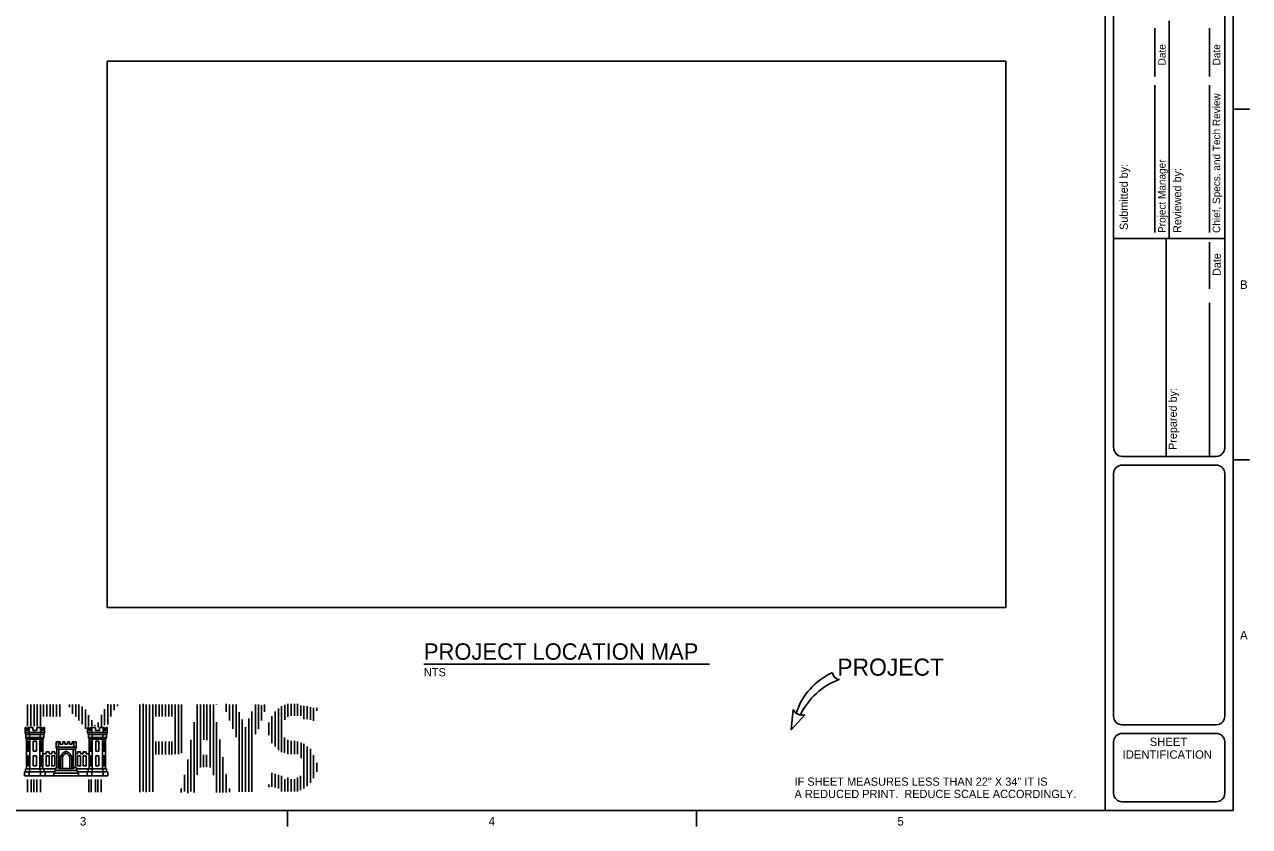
# Model space of a CAD drawing. Extents: x -1.36 to 2.79, y 0.03 to 1.79.
# Drawn here: x 1.298 to 2.791, y 0.043 to 1.02 of the extents above; entities that cross this region are included whole.
import ezdxf

# ---------------------------------------------------------------- set-up
doc = ezdxf.new("R2010")
doc.units = 0
for name, color, linetype in [('FL9BG-BS0001 - G-ANNO-TEXT', 7, 'Continuous'), ('G-ANNO-SYMB', 7, 'Continuous'), ('G-ANNO-TEXT', 7, 'Continuous'), ('G-ANNO-TTLB', 7, 'Continuous')]:
    doc.layers.add(name, color=color, linetype=linetype)

msp = doc.modelspace()

# ---------------------------------------------------------------- linework, layer by layer
at = {"layer": 'G-ANNO-SYMB'}
msp.add_line((2.1329, 0.2408), (1.7848, 0.2408), dxfattribs=at)
msp.add_lwpolyline([(1.399, 0.9753), (2.4939, 0.9753), (2.4939, 0.3098), (1.399, 0.3098)], close=True, dxfattribs=at)
for points in [[(2.249, 0.1789), (2.2323, 0.1608), (2.2348, 0.1854)], [(2.249, 0.1789), (2.2323, 0.1608), (2.2348, 0.1853)], [(2.2434, 0.1787), (2.2434, 0.1787)], [(2.2434, 0.1787), (2.2434, 0.1787)]]:
    msp.add_lwpolyline(points, dxfattribs=at)
for centre, radius, start, end in [((2.3157, 0.1561), 0.0813, 114.1414, 162.1394), ((2.3157, 0.1561), 0.0813, 114.1414, 162.1394), ((2.2914, 0.231), 0.00894, 184.9032, 266.6327), ((2.2914, 0.231), 0.00894, 184.9032, 266.6327), ((2.3203, 0.1422), 0.0851, 110.2554, 154.6222), ((2.3203, 0.1422), 0.0851, 110.2554, 154.6168), ((2.2457, 0.1907), 0.0122, 205.9222, 285.6211), ((2.2457, 0.1907), 0.0122, 205.9222, 258.8897), ((2.2457, 0.1907), 0.0122, 232.4837, 258.8897), ((2.2457, 0.1907), 0.0122, 258.8991, 285.6211), ((2.3203, 0.1422), 0.0851, 154.6168, 154.6222)]:
    msp.add_arc(centre, radius, start, end, dxfattribs=at)
at = {"layer": 'G-ANNO-TEXT'}
for p, q in [((1.3021, 0.1652), (1.3021, 0.1916)), ((1.306, 0.1652), (1.306, 0.1916)), ((1.3099, 0.1652), (1.3099, 0.1916)), ((1.3138, 0.1649), (1.3138, 0.1916)), ((1.3177, 0.1652), (1.3177, 0.1916)), ((1.3216, 0.1769), (1.3216, 0.1916)), ((1.3255, 0.1769), (1.3255, 0.1916)), ((1.3294, 0.1769), (1.3294, 0.1916)), ((1.3333, 0.1769), (1.3333, 0.1916)), ((1.3372, 0.1769), (1.3372, 0.1916)), ((1.3412, 0.1769), (1.3412, 0.1916)), ((1.3529, 0.1883), (1.3529, 0.1916)), ((1.3568, 0.1803), (1.3568, 0.1916)), ((1.3607, 0.1769), (1.3607, 0.1916)), ((1.3646, 0.172), (1.3646, 0.1916)), ((1.3685, 0.1674), (1.3685, 0.1889)), ((1.3724, 0.1852), (1.3724, 0.1618)), ((1.3958, 0.1664), (1.3958, 0.1858)), ((1.3997, 0.167), (1.3997, 0.1919)), ((1.4036, 0.1769), (1.4036, 0.1916)), ((1.4076, 0.1846), (1.4076, 0.1919)), ((1.4115, 0.1895), (1.4115, 0.1916)), ((1.4388, 0.0847), (1.4388, 0.1916)), ((1.4427, 0.0853), (1.4427, 0.1922)), ((1.4466, 0.0847), (1.4466, 0.1916)), ((1.4505, 0.085), (1.4505, 0.1916)), ((1.4544, 0.085), (1.4544, 0.1916)), ((1.4583, 0.1769), (1.4583, 0.1916)), ((1.4622, 0.1769), (1.4622, 0.1916)), ((1.4661, 0.1769), (1.4661, 0.1916)), ((1.47, 0.1769), (1.47, 0.1916)), ((1.4739, 0.1769), (1.4739, 0.1916)), ((1.4779, 0.1769), (1.4779, 0.1916)), ((1.4818, 0.1311), (1.4818, 0.1916)), ((1.4857, 0.1311), (1.4857, 0.1916)), ((1.4896, 0.1323), (1.4896, 0.1916)), ((1.5088, 0.1057), (1.5088, 0.1913)), ((1.5127, 0.1148), (1.5127, 0.1913)), ((1.5166, 0.1484), (1.5166, 0.1913)), ((1.5205, 0.1481), (1.5205, 0.1913)), ((1.5244, 0.1148), (1.5244, 0.1913)), ((1.5283, 0.1055), (1.5283, 0.1913)), ((1.5322, 0.191), (1.5322, 0.1913)), ((1.5439, 0.1824), (1.5439, 0.1922)), ((1.548, 0.1721), (1.548, 0.1916)), ((1.5521, 0.1618), (1.5521, 0.1916)), ((1.5561, 0.1515), (1.5561, 0.1916)), ((1.5599, 0.085), (1.5599, 0.1821)), ((1.5752, 0.1913), (1.5752, 0.1916)), ((1.5752, 0.085), (1.5752, 0.183)), ((1.5796, 0.1553), (1.5796, 0.1916)), ((1.5833, 0.1615), (1.5833, 0.1913)), ((1.5871, 0.172), (1.5871, 0.1907)), ((1.5908, 0.1827), (1.5908, 0.1913)), ((1.6036, 0.1403), (1.6036, 0.183)), ((1.6075, 0.136), (1.6075, 0.1867)), ((1.6114, 0.1335), (1.6114, 0.1895)), ((1.6153, 0.1729), (1.6153, 0.191)), ((1.6192, 0.1763), (1.6192, 0.1922)), ((1.6231, 0.1775), (1.6231, 0.1922)), ((1.627, 0.1775), (1.627, 0.1922)), ((1.6309, 0.1775), (1.6309, 0.1922)), ((1.6348, 0.1775), (1.6348, 0.1901)), ((1.6387, 0.1738), (1.6387, 0.1898)), ((1.6426, 0.1895), (1.6426, 0.1738)), ((1.6466, 0.1883), (1.6466, 0.1726)), ((1.6505, 0.1726), (1.6505, 0.1876)), ((1.6544, 0.1836), (1.6544, 0.1876)), ((1.3763, 0.1652), (1.3763, 0.1784)), ((1.3802, 0.1652), (1.3802, 0.1723)), ((1.3841, 0.1655), (1.3841, 0.1664)), ((1.388, 0.164), (1.388, 0.1695)), ((1.3919, 0.1646), (1.3919, 0.179)), ((1.5049, 0.0844), (1.5049, 0.1699)), ((1.5322, 0.0841), (1.5322, 0.17)), ((1.5636, 0.085), (1.5636, 0.1732)), ((1.5717, 0.085), (1.5717, 0.1744)), ((1.5958, 0.1541), (1.5958, 0.1695)), ((1.5997, 0.1443), (1.5997, 0.1772)), ((1.6505, 0.1717), (1.6505, 0.1726)), ((1.299, 0.1634), (1.3005, 0.1634)), ((1.299, 0.1572), (1.299, 0.1634)), ((1.299, 0.1572), (1.3108, 0.1572)), ((1.299, 0.1572), (1.2999, 0.1551)), ((1.2999, 0.1551), (1.3108, 0.1551)), ((1.2999, 0.1551), (1.2999, 0.1514)), ((1.2999, 0.1514), (1.3108, 0.1514)), ((1.3008, 0.1492), (1.2999, 0.1514)), ((1.3005, 0.1634), (1.3005, 0.1597)), ((1.3005, 0.1597), (1.3024, 0.1597)), ((1.3005, 0.1572), (1.3015, 0.1572)), ((1.3024, 0.1634), (1.3083, 0.1634)), ((1.3024, 0.1634), (1.3024, 0.1597)), ((1.304, 0.1572), (1.304, 0.1634)), ((1.3043, 0.1551), (1.304, 0.1572)), ((1.3043, 0.1551), (1.3043, 0.1514)), ((1.3043, 0.1514), (1.3046, 0.1492)), ((1.3083, 0.1597), (1.3083, 0.1634)), ((1.3083, 0.1597), (1.3108, 0.1597)), ((1.3133, 0.1597), (1.3108, 0.1597)), ((1.3227, 0.1572), (1.3108, 0.1572)), ((1.3218, 0.1551), (1.3108, 0.1551)), ((1.3218, 0.1514), (1.3108, 0.1514)), ((1.3133, 0.1597), (1.3133, 0.1634)), ((1.3193, 0.1634), (1.3133, 0.1634)), ((1.3174, 0.1514), (1.3171, 0.1492)), ((1.3174, 0.1551), (1.3177, 0.1572)), ((1.3174, 0.1551), (1.3174, 0.1514)), ((1.3177, 0.1572), (1.3177, 0.1634)), ((1.3193, 0.1634), (1.3193, 0.1597)), ((1.3212, 0.1597), (1.3193, 0.1597)), ((1.3212, 0.1572), (1.3202, 0.1572)), ((1.3208, 0.1492), (1.3218, 0.1514)), ((1.3227, 0.1634), (1.3212, 0.1634)), ((1.3212, 0.1634), (1.3212, 0.1597)), ((1.3227, 0.1572), (1.3218, 0.1551)), ((1.3218, 0.1551), (1.3218, 0.1514)), ((1.3227, 0.1572), (1.3227, 0.1634)), ((1.3752, 0.1634), (1.3768, 0.1634)), ((1.3752, 0.1572), (1.3752, 0.1634)), ((1.3752, 0.1572), (1.3871, 0.1572)), ((1.3752, 0.1572), (1.3761, 0.1551)), ((1.3761, 0.1551), (1.3871, 0.1551)), ((1.3761, 0.1551), (1.3761, 0.1514)), ((1.3761, 0.1514), (1.3871, 0.1514)), ((1.3771, 0.1492), (1.3761, 0.1514)), ((1.3768, 0.1634), (1.3768, 0.1597)), ((1.3768, 0.1597), (1.3786, 0.1597)), ((1.3768, 0.1572), (1.3777, 0.1572)), ((1.3786, 0.1634), (1.3846, 0.1634)), ((1.3786, 0.1634), (1.3786, 0.1597)), ((1.3802, 0.1572), (1.3802, 0.1634)), ((1.3805, 0.1551), (1.3802, 0.1572)), ((1.3805, 0.1551), (1.3805, 0.1514)), ((1.3805, 0.1514), (1.3808, 0.1492)), ((1.3846, 0.1597), (1.3846, 0.1634)), ((1.3846, 0.1597), (1.3871, 0.1597)), ((1.3896, 0.1597), (1.3871, 0.1597)), ((1.399, 0.1572), (1.3871, 0.1572)), ((1.398, 0.1551), (1.3871, 0.1551)), ((1.398, 0.1514), (1.3871, 0.1514)), ((1.3896, 0.1597), (1.3896, 0.1634)), ((1.3955, 0.1634), (1.3896, 0.1634)), ((1.3936, 0.1514), (1.3933, 0.1492)), ((1.3936, 0.1551), (1.394, 0.1572)), ((1.3936, 0.1551), (1.3936, 0.1514)), ((1.394, 0.1572), (1.394, 0.1634)), ((1.3955, 0.1634), (1.3955, 0.1597)), ((1.3974, 0.1597), (1.3955, 0.1597)), ((1.3974, 0.1572), (1.3965, 0.1572)), ((1.3971, 0.1492), (1.398, 0.1514)), ((1.399, 0.1634), (1.3974, 0.1634)), ((1.3974, 0.1634), (1.3974, 0.1597)), ((1.399, 0.1572), (1.398, 0.1551)), ((1.398, 0.1551), (1.398, 0.1514)), ((1.399, 0.1572), (1.399, 0.1634)), ((1.5674, 0.085), (1.5674, 0.1637)), ((1.6151, 0.1326), (1.6151, 0.1511)), ((1.3008, 0.1492), (1.3108, 0.1492)), ((1.3008, 0.1492), (1.3008, 0.113)), ((1.3021, 0.1345), (1.3021, 0.1468)), ((1.3021, 0.1468), (1.3033, 0.1468)), ((1.3033, 0.1345), (1.3021, 0.1345)), ((1.3033, 0.1345), (1.3033, 0.1468)), ((1.3046, 0.1492), (1.3046, 0.113)), ((1.309, 0.1468), (1.309, 0.1345)), ((1.309, 0.1468), (1.3108, 0.1468)), ((1.309, 0.1345), (1.3108, 0.1345)), ((1.3208, 0.1492), (1.3108, 0.1492)), ((1.3127, 0.1468), (1.3108, 0.1468)), ((1.3127, 0.1345), (1.3108, 0.1345)), ((1.3127, 0.1468), (1.3127, 0.1345)), ((1.3171, 0.1492), (1.3171, 0.113)), ((1.3183, 0.1345), (1.3183, 0.1468)), ((1.3196, 0.1468), (1.3183, 0.1468)), ((1.3183, 0.1345), (1.3196, 0.1345)), ((1.3196, 0.1345), (1.3196, 0.1468)), ((1.3208, 0.1492), (1.3208, 0.113)), ((1.3368, 0.1461), (1.3368, 0.1394)), ((1.3368, 0.1461), (1.3418, 0.1461)), ((1.3368, 0.1394), (1.349, 0.1394)), ((1.3377, 0.1372), (1.3368, 0.1394)), ((1.3374, 0.1372), (1.349, 0.1372)), ((1.3377, 0.1375), (1.3377, 0.1148)), ((1.3396, 0.1461), (1.3396, 0.1394)), ((1.3402, 0.1136), (1.3402, 0.1372)), ((1.3418, 0.1461), (1.3418, 0.1431)), ((1.3418, 0.1431), (1.3449, 0.1431)), ((1.3449, 0.1461), (1.3449, 0.1431)), ((1.3449, 0.1461), (1.3474, 0.1461)), ((1.3474, 0.1431), (1.3474, 0.1461)), ((1.3474, 0.1431), (1.3505, 0.1431)), ((1.3611, 0.1394), (1.349, 0.1394)), ((1.3605, 0.1372), (1.349, 0.1372)), ((1.3505, 0.1431), (1.3505, 0.1461)), ((1.353, 0.1461), (1.3505, 0.1461)), ((1.353, 0.1461), (1.353, 0.1431)), ((1.3562, 0.1431), (1.353, 0.1431)), ((1.3562, 0.1461), (1.3562, 0.1431)), ((1.3611, 0.1461), (1.3562, 0.1461)), ((1.3577, 0.1136), (1.3577, 0.1372)), ((1.3583, 0.1461), (1.3583, 0.1394)), ((1.3602, 0.1372), (1.3611, 0.1394)), ((1.3602, 0.1375), (1.3602, 0.1148)), ((1.3611, 0.1461), (1.3611, 0.1394)), ((1.3771, 0.1492), (1.3871, 0.1492)), ((1.3771, 0.1492), (1.3771, 0.113)), ((1.3783, 0.1345), (1.3783, 0.1468)), ((1.3783, 0.1468), (1.3796, 0.1468)), ((1.3796, 0.1345), (1.3783, 0.1345)), ((1.3796, 0.1345), (1.3796, 0.1468)), ((1.3808, 0.1492), (1.3808, 0.113)), ((1.3852, 0.1468), (1.3852, 0.1345)), ((1.3852, 0.1468), (1.3871, 0.1468)), ((1.3852, 0.1345), (1.3871, 0.1345)), ((1.3971, 0.1492), (1.3871, 0.1492)), ((1.389, 0.1468), (1.3871, 0.1468)), ((1.389, 0.1345), (1.3871, 0.1345)), ((1.389, 0.1468), (1.389, 0.1345)), ((1.3933, 0.1492), (1.3933, 0.113)), ((1.3946, 0.1345), (1.3946, 0.1468)), ((1.3958, 0.1468), (1.3946, 0.1468)), ((1.3946, 0.1345), (1.3958, 0.1345)), ((1.3958, 0.1345), (1.3958, 0.1468)), ((1.3971, 0.1492), (1.3971, 0.113)), ((1.4583, 0.1305), (1.4583, 0.1465)), ((1.4621, 0.1305), (1.4621, 0.1465)), ((1.4661, 0.1305), (1.4661, 0.1465)), ((1.4699, 0.1305), (1.4699, 0.1465)), ((1.4743, 0.1305), (1.4743, 0.1465)), ((1.4777, 0.1305), (1.4777, 0.1465)), ((1.501, 0.1485), (1.501, 0.0853)), ((1.5361, 0.0844), (1.5361, 0.1487)), ((1.6192, 0.1311), (1.6192, 0.1486)), ((1.623, 0.1311), (1.623, 0.1471)), ((1.627, 0.1311), (1.627, 0.1471)), ((1.6308, 0.1311), (1.6308, 0.1465)), ((1.6351, 0.1262), (1.6351, 0.1449)), ((1.6387, 0.089), (1.6387, 0.1434)), ((1.6426, 0.1403), (1.6426, 0.0921)), ((1.6466, 0.1375), (1.6466, 0.1369)), ((1.6466, 0.1366), (1.6466, 0.0961)), ((1.3021, 0.1166), (1.3021, 0.1289)), ((1.3033, 0.1289), (1.3021, 0.1289)), ((1.3033, 0.1166), (1.3033, 0.1289)), ((1.309, 0.1289), (1.309, 0.1166)), ((1.309, 0.1289), (1.3108, 0.1289)), ((1.3127, 0.1289), (1.3108, 0.1289)), ((1.3127, 0.1289), (1.3127, 0.1166)), ((1.3183, 0.1166), (1.3183, 0.1289)), ((1.3183, 0.1289), (1.3196, 0.1289)), ((1.3196, 0.1166), (1.3196, 0.1289)), ((1.3208, 0.1314), (1.3246, 0.1314)), ((1.3246, 0.1339), (1.3283, 0.1339)), ((1.3246, 0.1339), (1.3246, 0.1314)), ((1.3246, 0.1289), (1.3283, 0.1289)), ((1.3246, 0.1289), (1.3246, 0.1166)), ((1.3283, 0.1339), (1.3283, 0.1314)), ((1.3283, 0.1314), (1.3315, 0.1314)), ((1.3283, 0.1289), (1.3283, 0.1166)), ((1.3315, 0.1339), (1.3352, 0.1339)), ((1.3315, 0.1339), (1.3315, 0.1314)), ((1.3315, 0.1289), (1.3352, 0.1289)), ((1.3315, 0.1289), (1.3315, 0.1166)), ((1.3352, 0.1339), (1.3352, 0.1314)), ((1.3352, 0.1314), (1.3377, 0.1314)), ((1.3352, 0.1289), (1.3352, 0.1166)), ((1.3377, 0.1314), (1.3377, 0.1148)), ((1.3421, 0.1136), (1.3421, 0.1277)), ((1.3446, 0.1136), (1.3446, 0.1277)), ((1.3533, 0.1136), (1.3533, 0.1277)), ((1.3558, 0.1136), (1.3558, 0.1277)), ((1.3627, 0.1314), (1.3602, 0.1314)), ((1.3602, 0.1314), (1.3602, 0.1148)), ((1.3665, 0.1339), (1.3627, 0.1339)), ((1.3627, 0.1339), (1.3627, 0.1314)), ((1.3665, 0.1289), (1.3627, 0.1289)), ((1.3627, 0.1289), (1.3627, 0.1166)), ((1.3665, 0.1339), (1.3665, 0.1314)), ((1.3696, 0.1314), (1.3665, 0.1314)), ((1.3665, 0.1289), (1.3665, 0.1166)), ((1.3733, 0.1339), (1.3696, 0.1339)), ((1.3696, 0.1339), (1.3696, 0.1314)), ((1.3733, 0.1289), (1.3696, 0.1289)), ((1.3696, 0.1289), (1.3696, 0.1166)), ((1.3733, 0.1339), (1.3733, 0.1314)), ((1.3771, 0.1314), (1.3733, 0.1314)), ((1.3733, 0.1289), (1.3733, 0.1166)), ((1.3783, 0.1166), (1.3783, 0.1289)), ((1.3796, 0.1289), (1.3783, 0.1289)), ((1.3796, 0.1166), (1.3796, 0.1289)), ((1.3852, 0.1289), (1.3852, 0.1166)), ((1.3852, 0.1289), (1.3871, 0.1289)), ((1.389, 0.1289), (1.3871, 0.1289)), ((1.389, 0.1289), (1.389, 0.1166)), ((1.3946, 0.1166), (1.3946, 0.1289)), ((1.3946, 0.1289), (1.3958, 0.1289)), ((1.3958, 0.1166), (1.3958, 0.1289)), ((1.4971, 0.1243), (1.4971, 0.0835)), ((1.5163, 0.1151), (1.5163, 0.1302)), ((1.52, 0.1151), (1.52, 0.1302)), ((1.54, 0.0844), (1.54, 0.1273)), ((1.6505, 0.1019), (1.6505, 0.1299)), ((1.6544, 0.1093), (1.6544, 0.1203)), ((1.2983, 0.1093), (1.3108, 0.1093)), ((1.2983, 0.1044), (1.2983, 0.1093)), ((1.2996, 0.113), (1.3108, 0.113)), ((1.2996, 0.1093), (1.2996, 0.113)), ((1.3021, 0.1166), (1.3033, 0.1166)), ((1.304, 0.1044), (1.304, 0.1093)), ((1.3043, 0.1093), (1.3043, 0.113)), ((1.309, 0.1166), (1.3108, 0.1166)), ((1.3127, 0.1166), (1.3108, 0.1166)), ((1.3365, 0.113), (1.3108, 0.113)), ((1.3352, 0.1093), (1.3108, 0.1093)), ((1.3174, 0.1093), (1.3174, 0.113)), ((1.3177, 0.1044), (1.3177, 0.1093)), ((1.3196, 0.1166), (1.3183, 0.1166)), ((1.3221, 0.1093), (1.3221, 0.113)), ((1.3233, 0.1044), (1.3233, 0.1093)), ((1.3246, 0.1166), (1.3283, 0.1166)), ((1.3315, 0.1166), (1.3352, 0.1166)), ((1.3315, 0.1163), (1.3315, 0.116)), ((1.334, 0.108), (1.334, 0.1044)), ((1.334, 0.108), (1.349, 0.108)), ((1.3352, 0.1111), (1.349, 0.1111)), ((1.3352, 0.1111), (1.3352, 0.108)), ((1.3365, 0.1148), (1.3396, 0.1148)), ((1.3365, 0.1111), (1.3365, 0.1148)), ((1.3396, 0.1136), (1.3396, 0.1148)), ((1.3396, 0.1136), (1.349, 0.1136)), ((1.3583, 0.1136), (1.349, 0.1136)), ((1.3627, 0.1111), (1.349, 0.1111)), ((1.364, 0.108), (1.349, 0.108)), ((1.3583, 0.1136), (1.3583, 0.1148)), ((1.3615, 0.1148), (1.3583, 0.1148)), ((1.3615, 0.1111), (1.3615, 0.1148)), ((1.3615, 0.113), (1.3871, 0.113)), ((1.3665, 0.1166), (1.3627, 0.1166)), ((1.3627, 0.1111), (1.3627, 0.108)), ((1.3627, 0.1093), (1.3871, 0.1093)), ((1.364, 0.108), (1.364, 0.1044)), ((1.3665, 0.1163), (1.3665, 0.116)), ((1.3733, 0.1166), (1.3696, 0.1166)), ((1.3746, 0.1044), (1.3746, 0.1093)), ((1.3758, 0.1093), (1.3758, 0.113)), ((1.3783, 0.1166), (1.3796, 0.1166)), ((1.3802, 0.1044), (1.3802, 0.1093)), ((1.3805, 0.1093), (1.3805, 0.113)), ((1.3852, 0.1166), (1.3871, 0.1166)), ((1.389, 0.1166), (1.3871, 0.1166)), ((1.3983, 0.113), (1.3871, 0.113)), ((1.3996, 0.1093), (1.3871, 0.1093)), ((1.3936, 0.1093), (1.3936, 0.113)), ((1.394, 0.1044), (1.394, 0.1093)), ((1.3958, 0.1166), (1.3946, 0.1166)), ((1.3983, 0.1093), (1.3983, 0.113)), ((1.3996, 0.1044), (1.3996, 0.1093)), ((1.4932, 0.1058), (1.4932, 0.0856)), ((1.5439, 0.106), (1.5439, 0.1068)), ((1.5439, 0.0844), (1.5439, 0.1053)), ((1.5997, 0.0911), (1.5997, 0.1084)), ((1.6036, 0.0905), (1.6036, 0.1068)), ((1.6075, 0.0893), (1.6075, 0.1059)), ((1.6114, 0.0878), (1.6114, 0.1047)), ((1.6345, 0.0871), (1.6345, 0.1047)), ((1.2983, 0.1044), (1.3996, 0.1044)), ((1.3021, 0.0847), (1.3021, 0.1001)), ((1.3062, 0.0847), (1.3062, 0.1001)), ((1.3096, 0.0847), (1.3096, 0.1001)), ((1.3133, 0.0847), (1.3133, 0.1001)), ((1.3177, 0.0847), (1.3177, 0.1001)), ((1.334, 0.1044), (1.349, 0.1044)), ((1.364, 0.1044), (1.349, 0.1044)), ((1.3765, 0.0847), (1.3765, 0.1001)), ((1.3796, 0.0847), (1.3796, 0.1001)), ((1.3846, 0.0847), (1.3846, 0.1001)), ((1.3877, 0.0847), (1.3877, 0.1001)), ((1.3918, 0.0847), (1.3918, 0.1001)), ((1.5958, 0.0908), (1.5958, 0.0939)), ((1.6114, 0.0853), (1.6114, 0.1007)), ((1.6155, 0.0853), (1.6155, 0.1007)), ((1.6192, 0.0853), (1.6192, 0.1025)), ((1.623, 0.0853), (1.623, 0.1007)), ((1.627, 0.0853), (1.627, 0.1007)), ((1.6308, 0.0853), (1.6308, 0.1025)), ((1.4893, 0.0844), (1.4893, 0.089)), ((1.5478, 0.0847), (1.5478, 0.089)), ((2.75, 0.0625), (2.75, 0.0625)), ((2.7708, 0.0625), (2.7708, 0.0625)), ((2.7708, 0.0625), (2.7708, 0.0625)), ((2.7708, 0.0625), (2.7708, 0.0625)), ((2.7708, 0.0625), (2.7708, 0.0625))]:
    msp.add_line(p, q, dxfattribs=at)
for centre, major_axis, start_param, end_param in [((1.3533, 0.1234), (-0.0121, 0), 5.08328, 5.912294), ((1.3446, 0.1234), (0.0121, 0), 0.370891, 1.199905), ((1.3533, 0.1234), (-0.00978, 0), 5.176037, 5.819538), ((1.3446, 0.1234), (0.00978, 0), 0.463648, 1.107149)]:
    msp.add_ellipse(centre, major_axis=major_axis, ratio=0.983507, start_param=start_param, end_param=end_param, dxfattribs=at)
at = {"layer": 'G-ANNO-TTLB'}
for p, q in [((2.6754, 1.0156), (2.6754, 0.9566)), ((2.6928, 1.0245), (2.6928, 0.7591)), ((2.7418, 1.0156), (2.7418, 0.9566)), ((2.6754, 0.9462), (2.6754, 0.7664)), ((2.7418, 0.9462), (2.7418, 0.7664)), ((2.7708, 0.9167), (2.7905, 0.9167)), ((2.6928, 0.7591), (2.6239, 0.7591)), ((2.6892, 0.7591), (2.6892, 0.4938)), ((2.7593, 0.7591), (2.6928, 0.7591)), ((2.7418, 0.698), (2.7418, 0.7549)), ((2.7418, 0.681), (2.7418, 0.495)), ((2.7708, 0.4896), (2.7905, 0.4896)), ((1.6188, 0.0625), (1.6188, 0.0428)), ((2.1167, 0.0625), (2.1167, 0.0428))]:
    msp.add_line(p, q, dxfattribs=at)
for points in [[(0.125, 1.7708), (2.6146, 1.7708), (2.6146, 0.0625), (0.125, 0.0625)], [(2.6146, 0.0625), (2.7708, 0.0625), (2.7708, 1.7708), (2.6146, 1.7708)]]:
    msp.add_lwpolyline(points, close=True, dxfattribs=at)
for points in [[(2.625, 1.2795), (2.625, 0.5042)], [(2.7605, 0.5042), (2.7605, 1.2795)], [(2.6355, 0.4938), (2.75, 0.4938)], [(2.6354, 0.4833), (2.75, 0.4833)], [(2.625, 0.4729), (2.625, 0.1771)], [(2.7604, 0.1771), (2.7604, 0.4729)], [(2.6354, 0.1667), (2.75, 0.1667)], [(2.6354, 0.1563), (2.75, 0.1563)], [(2.625, 0.0833), (2.625, 0.1458)], [(2.7604, 0.1458), (2.7604, 0.0833)], [(2.75, 0.0729), (2.6354, 0.0729)]]:
    msp.add_lwpolyline(points, dxfattribs=at)
for centre, start, end in [((2.6355, 0.5042), 180, 270), ((2.75, 0.5042), 270, 0), ((2.6354, 0.4729), 90, 180), ((2.75, 0.4729), 360, 90), ((2.6354, 0.1771), 180, 270), ((2.75, 0.1771), 270, 0), ((2.6354, 0.1458), 90, 180.0158), ((2.75, 0.1458), 0.0158, 90), ((2.6354, 0.0833), 180.0158, 270), ((2.75, 0.0833), 270, 0.0158)]:
    msp.add_arc(centre, 0.0104, start, end, dxfattribs=at)

# ---------------------------------------------------------------- texts
at = {"layer": 'FL9BG-BS0001 - G-ANNO-TEXT'}
for s, p in [('IF SHEET MEASURES LESS THAN 22" X 34" IT IS ', (2.2363, 0.0925)), ('A REDUCED PRINT.  REDUCE SCALE ACCORDINGLY.', (2.2363, 0.0775))]:
    msp.add_text(s, height=0.01, dxfattribs=at).set_placement(p)
at = {"layer": 'G-ANNO-SYMB'}
for s, height, p in [('PROJECT LOCATION MAP', 0.02, (1.7848, 0.246)), ('PROJECT', 0.02083, (2.2884, 0.2266)), ('NTS', 0.01, (1.7848, 0.2258))]:
    msp.add_text(s, height=height, dxfattribs=at).set_placement(p)
at = {"layer": 'G-ANNO-TEXT'}
for s, height, p in [('Date', 0.00911, (2.6884, 0.9703)), ('Date', 0.00911, (2.7548, 0.9703)), ('Chief, Specs. and Tech Review ', 0.009115, (2.7548, 0.7661)), ('Project Manager', 0.009115, (2.6883, 0.7661)), ('Submitted by:', 0.009843, (2.6423, 0.7697)), ('Reviewed by:', 0.009843, (2.7074, 0.7661)), ('Date', 0.00984, (2.7556, 0.7136)), ('Prepared by:', 0.009843, (2.702, 0.5017))]:
    msp.add_text(s, height=height, rotation=90, dxfattribs=at).set_placement(p)
for s, height, p in [('B', 0.0104, (2.779, 0.6979)), ('A', 0.0104, (2.779, 0.2708)), ('SHEET', 0.01025, (2.669, 0.1409)), ('IDENTIFICATION', 0.010253, (2.6359, 0.1254)), ('3', 0.0104, (1.3658, 0.044)), ('4', 0.0104, (1.8637, 0.044)), ('5', 0.0104, (2.3616, 0.044))]:
    msp.add_text(s, height=height, dxfattribs=at).set_placement(p)

doc.saveas('drawing.dxf')
